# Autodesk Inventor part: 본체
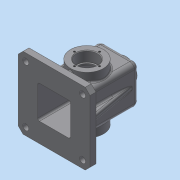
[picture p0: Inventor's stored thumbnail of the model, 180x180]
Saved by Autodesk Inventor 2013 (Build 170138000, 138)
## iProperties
Created: 2018-10
Part Number: 본체
Material: 일반
Document SubType Name: Modeling
Designer: Administrator
Density: 1 g/cm^3
Author: Administrator
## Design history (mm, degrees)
sketch "스케치1"
  geometry: L1 (-32.5, -32.5)-(32.5, -32.5); L2 (32.5, -32.5)-(32.5, 32.5); L3 (32.5, 32.5)-(-32.5, 32.5); L4 (-32.5, 32.5)-(-32.5, -32.5); L5 (-32.5, -32.5)-(32.5, 32.5); L6 (32.5, -32.5)-(-32.5, 32.5); 1 further point
  constraints: 12 end point, 2 midpoint, 2 parallel, 1 horizontal, 1 perpendicular
  dimensions: "d0" = 65 distance of L3.end L2.end; "d1" = 65 distance of L2.end L1.end
extrude "돌출1" new body sketch "스케치1" stored distance "d2" = 110; taper "d3" = 0 deg
sketch "스케치2"
  geometry: L1 (27.5, 27.5)-(-27.5, 27.5); L2 (-27.5, 27.5)-(-27.5, -27.5); L3 (-27.5, -27.5)-(27.5, -27.5); L4 (27.5, -27.5)-(27.5, 27.5); L5 (27.5, 27.5)-(-27.5, -27.5); L6 (-27.5, 27.5)-(27.5, -27.5); 1 further point
  constraints: 12 end point, 2 midpoint, 2 parallel, 1 horizontal, 1 perpendicular
  dimensions: "d4" = 55 distance of L3.end L2.end; "d5" = 55 distance of L2.end L1.end
extrude "돌출2" cut sketch "스케치2" distance "d6" = 105; taper "d7" = 0 deg
sketch "스케치3"
  geometry: C1 r 17.5 at (32.5, -55); C2 r 27.5 at (32.5, -55); 1 further point
  constraints: 2 centre point, 2 coincident
  dimensions: "d8" = 35 diameter of C1; "d9" = 55 diameter of C2
extrude "돌출3" join sketch "스케치3" distance "d10" = 15; taper "d11" = 0 deg
sketch "스케치4"
  geometry: C1 r 17.5 at (32.5, -55); C2 r 27.5 at (32.5, -55); 1 further point
  constraints: 2 centre point, 2 coincident
  dimensions: "d12" = 35 diameter of C1; "d13" = 55 diameter of C2
extrude "돌출4" join sketch "스케치4" distance "d14" = 15; taper "d15" = 0 deg
sketch "스케치5"
  geometry: C1 r 17.5 at (0, 0) reference; C2 r 27.5 at (0, 0) reference; C3 r 17.5 at (0, 0)
  constraints: 1 centre point, 1 coincident
  dimensions: "d16" = 35 diameter of C3
extrude "돌출5" cut sketch "스케치5" distance "d17" = 17; taper "d18" = 0 deg
sketch "스케치6"
  geometry: C1 r 17.5 at (0, 0) reference; C2 r 27.5 at (0, 0) reference; C3 r 17.5 at (0, 0)
  constraints: 1 centre point, 1 coincident
  dimensions: "d19" = 35 diameter of C3
extrude "돌출6" cut sketch "스케치6" distance "d20" = 17; taper "d21" = 0 deg
sketch "스케치7"
  geometry: C1 r 17.5 at (0, 0) reference; C2 r 15 at (0, 0)
  constraints: 1 centre point, 1 coincident
  dimensions: "d22" = 30 diameter of C2
extrude "돌출7" cut sketch "스케치7" stored distance "d23" = 17; taper "d24" = 0 deg
sketch "스케치8"
  geometry: C1 r 20 at (0, 0); 1 further point
  constraints: 1 centre point, 1 coincident
  dimensions: "d25" = 40 diameter of C1
extrude "돌출8" join sketch "스케치8" distance "d26" = 10; taper "d27" = -7 deg
sketch "스케치9"
  geometry: C1 r 18.772 at (0, 0) reference; 1 further point
  constraints: 1 coincident
hole "구멍1" sketch "스케치9" at (0, 0) diameter "d28" = 22.835; stored, may be unused: countersink angle "d32" = 90 deg, drill point angle "d34" = 118 deg; dims "d29" = 6, "d30" = 4, "d31" = 2, "d33" = 8
sketch "스케치10"
  geometry: L1 (-32.5, -32.5)-(32.5, -32.5) reference; L2 (32.5, -32.5)-(32.5, 32.5) reference; L3 (32.5, 32.5)-(-32.5, 32.5) reference; L4 (-32.5, 32.5)-(-32.5, -32.5) reference; L5 (60, 60)-(-60, 60); L6 (-60, 60)-(-60, -60); L7 (-60, -60)-(60, -60); L8 (60, -60)-(60, 60); L9 (60, 60)-(-60, -60); L10 (-60, 60)-(60, -60); 1 further point
  constraints: 12 end point, 2 midpoint, 2 parallel, 1 horizontal, 1 perpendicular
  dimensions: "d35" = 120 distance of L7.end L6.end; "d36" = 120 distance of L6.end L5.end
extrude "돌출9" join sketch "스케치10" distance "d37" = 10; taper "d38" = 0 deg
chamfer "모따기1" distance "d39" = 8; stored, may be unused: second distance "d40" = 2, angle "d41" = 45 deg
sketch "스케치11"
  geometry: L1 (-48, -45)-(-42.093, -11.501); L2 (-60, -55)-(-60, -45) reference; L3 (52, -45)-(-52, -45) reference; 1 further point
  constraints: 2 end point, 1 point on line
  dimensions: "d42" = 10 deg angle of L1 L2; "d43" = 12 distance from line of L1.start L2
feature "리브1" sketch "스케치11" dims "d44" = 1, "d45" = 10, "d46" = 0, "d47" = 0, "d48" = 1, "d49" = 1
fillet "모깎기1" dims "d50" = 3
fillet "모깎기2" dims "d51" = 3
fillet "모깎기3" dims "d52" = 8
fillet "모깎기4" dims "d53" = 8
fillet "모깎기5" dims "d54" = 3
fillet "모깎기6" dims "d55" = 3
fillet "모깎기7" dims "d56" = 3
fillet "모깎기8" dims "d57" = 3
sketch "스케치12"
  geometry: L1 (-42.975, 42.5)-(-31.831, 42.5); L2 (47, 27.5)-(-55, 27.5) reference; 1 further point
  constraints: 2 end point, 1 horizontal
  dimensions: "d58" = 15 distance between parallel lines of L2 L1
feature "리브2" sketch "스케치12" dims "d59" = 1, "d60" = 6, "d61" = 0, "d62" = 0, "d63" = 1, "d64" = 1
sketch "스케치14"
  geometry: L1 (0, 0)-(0, 21); C1 r 17.5 at (0, 0) reference; 1 further point
  constraints: 2 end point, 1 coincident, 1 vertical
  dimensions: "d65" = 21 distance of L1.start L1.end
hole "구멍2" sketch "스케치14" at (0, 21) diameter "d66" = 3.242; stored, may be unused: countersink angle "d70" = 90 deg, drill point angle "d72" = 118 deg; dims "d67" = 8, "d68" = 4, "d69" = 2, "d71" = 10
fillet "모깎기9" dims "d76" = 3
chamfer "모따기2" distance "d77" = 1; stored, may be unused: second distance "d78" = 2, angle "d79" = 45 deg
fillet "모깎기10" dims "d80" = 0.3
chamfer "모따기3" distance "d81" = 1; stored, may be unused: second distance "d82" = 2, angle "d83" = 45 deg
fillet "모깎기11" dims "d84" = 3
fillet "모깎기12" dims "d85" = 3
fillet "모깎기13" dims "d86" = 3
fillet "모깎기14" dims "d87" = 1
fillet "모깎기15" dims "d88" = 3
sketch "스케치15"
  geometry: L1 (47.5, 47.5)-(-47.5, 47.5); L2 (-47.5, 47.5)-(-47.5, -47.5); L3 (-47.5, -47.5)-(47.5, -47.5); L4 (47.5, -47.5)-(47.5, 47.5); L5 (47.5, 47.5)-(-47.5, -47.5); L6 (-47.5, 47.5)-(47.5, -47.5); C1 r 5 at (-47.5, -47.5); 1 further point
  constraints: 12 end point, 2 midpoint, 2 parallel, 1 centre point, 1 coincident, 1 horizontal, 1 perpendicular
  dimensions: "d89" = 95 distance of L3.end L2.end; "d90" = 95 distance of L2.end L1.end; "d91" = 10 diameter of C1
extrude "돌출10" cut sketch "스케치15" stored distance "d92" = 10; taper "d93" = 0 deg
sketch "스케치16"
  geometry: L1 (84.5, -102)-(-35.5, -102) reference; L2 (-35.5, -102)-(-35.5, -92) reference; L3 (-35.5, -92)-(-4.123, -92) reference; L4 (18.5, -91)-(0, -91) reference; L5 (18.5, -76.904)-(18.5, -91) reference; L6 (30.5, -91)-(30.5, -76.904) reference; L7 (49, -91)-(30.5, -91) reference; L8 (53.123, -92)-(84.5, -92) reference; L9 (84.5, -92)-(84.5, -102) reference; L10 (0, -65.166)-(0, -91) reference; L11 (0, 0)-(0, -28.834) reference; L12 (0, 0)-(49, 0) reference; L13 (49, -28.834)-(49, 0) reference; L14 (49, -91)-(49, -65.166) reference; L15 (-8, 0)-(-8, -91) reference; L16 (5.728, 18)-(43.272, 18) reference; C1 r 17.5 at (24.5, -47) reference; A1 r 30.5 centre (24.5, -47) between (0, -65.166) and (18.5, -76.904) reference; A2 r 30.5 centre (24.5, -47) between (49, -28.834) and (0, -28.834) reference; A3 r 30.5 centre (24.5, -47) between (30.5, -76.904) and (49, -65.166) reference; 1 further point
  constraints: 2 vertical alignment, 3 other
  dimensions: "d94" = 32.5 distance from line of point (24.5, -8) L15; "d95" = 26 distance from line of point (24.5, -8) L16
feature "엠보싱1" sketch "스케치16" dims "d8" = 35, "d9" = 55, "d96" = 0.5, "d97" = 0
node "솔리드1"
mirror "대칭1"
mirror "대칭2"
pattern_circular "원형 패턴1" dims angle "d74" = 360 deg
mirror "대칭3"
mirror "대칭4"
mirror "대칭5"
node "절단 모서리 투영1"
